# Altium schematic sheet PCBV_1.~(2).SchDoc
size A4; SheetNumber: 1; SheetTotal: 1
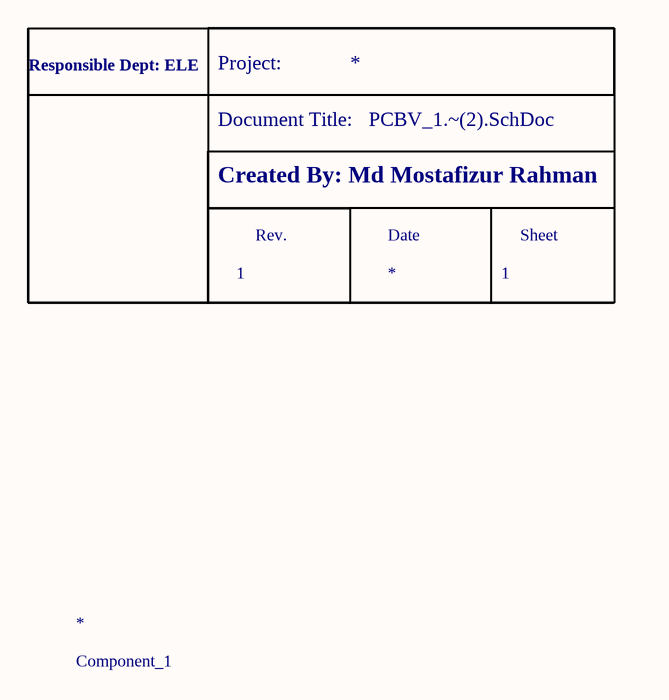
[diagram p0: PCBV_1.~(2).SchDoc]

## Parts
(Parts that share a designator on the sheet are numbered #1, #2 ... from top to bottom, then left to right.)
*#1  HSHL Title Block  (value not drawn)  (graphical)
*#2  Component_1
